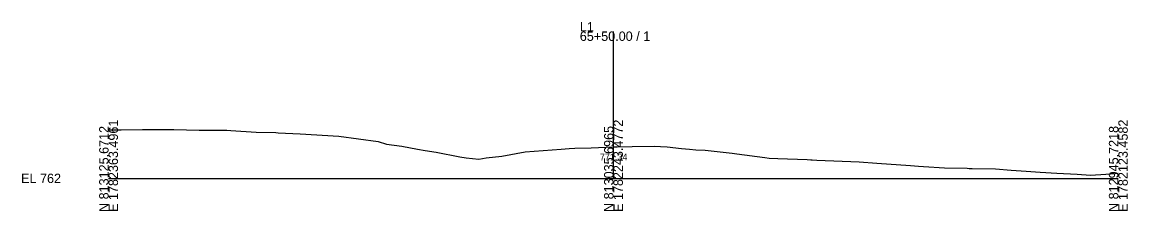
# Model space of a CAD drawing. Extents: x 5574 to 10203, y -10 to 9546.
# Drawn here: x 7574.3 to 7902.8, y 2990.3 to 3046.5 of the extents above; entities that cross this region are included whole.
import ezdxf

# ---------------------------------------------------------------- set-up
doc = ezdxf.new("R2010")
doc.units = 0
for name, color, linetype in [('Exist Cross Section Cell', 7, 'Continuous'), ('Exist XS Center Line Elevation Label', 7, 'Continuous'), ('Exist XS Ground Line', 7, 'Continuous')]:
    doc.layers.add(name, color=color, linetype=linetype)

msp = doc.modelspace()

# ---------------------------------------------------------------- linework, layer by layer
at = {"layer": 'Exist Cross Section Cell'}
for p, q in [((7750, 3000), (7750, 3043.71)), ((7600, 3000), (7750, 3000)), ((7750, 3000), (7900, 3000))]:
    msp.add_line(p, q, dxfattribs=at)
at = {"layer": 'Exist XS Ground Line'}
for p, q in [((7600, 3014.43), (7603.78, 3014.44)), ((7603.78, 3014.44), (7610.06, 3014.52)), ((7610.06, 3014.52), (7617.29, 3014.57)), ((7617.29, 3014.57), (7619.39, 3014.55)), ((7619.39, 3014.55), (7626.94, 3014.3)), ((7626.94, 3014.3), (7633.7, 3014.32)), ((7633.7, 3014.32), (7635.09, 3014.3)), ((7635.09, 3014.3), (7636.33, 3014.26)), ((7636.33, 3014.26), (7643.86, 3013.72)), ((7643.86, 3013.72), (7649.69, 3013.6)), ((7649.69, 3013.6), (7650.4, 3013.58)), ((7650.4, 3013.58), (7656.88, 3013.29)), ((7656.88, 3013.29), (7668.44, 3012.55)), ((7668.44, 3012.55), (7680.14, 3010.95)), ((7680.14, 3010.95), (7682.61, 3010.19)), ((7682.61, 3010.19), (7687.13, 3009.61)), ((7687.13, 3009.61), (7691.73, 3008.65)), ((7750, 3009.34), (7751.08, 3009.38)), ((7751.08, 3009.38), (7755.59, 3009.48)), ((7755.59, 3009.48), (7762.08, 3009.61)), ((7762.08, 3009.61), (7763.98, 3009.52)), ((7763.98, 3009.52), (7765.99, 3009.43)), ((7765.99, 3009.43), (7770.26, 3008.88)), ((7691.73, 3008.65), (7694.07, 3008.33)), ((7694.07, 3008.33), (7697.37, 3007.76)), ((7697.37, 3007.76), (7704.31, 3006.41)), ((7704.31, 3006.41), (7706.24, 3006.13)), ((7706.24, 3006.13), (7709.96, 3005.76)), ((7712.14, 3006.06), (7716.88, 3006.62)), ((7716.88, 3006.62), (7723.79, 3007.87)), ((7723.79, 3007.87), (7734.44, 3008.69)), ((7734.44, 3008.69), (7736.83, 3008.85)), ((7736.83, 3008.85), (7738.53, 3008.95)), ((7738.53, 3008.95), (7743.33, 3009.11)), ((7743.33, 3009.11), (7750, 3009.34)), ((7770.26, 3008.88), (7772.64, 3008.65)), ((7772.64, 3008.65), (7774.48, 3008.53)), ((7774.48, 3008.53), (7777.24, 3008.43)), ((7777.24, 3008.43), (7785.28, 3007.45)), ((7785.28, 3007.45), (7786.65, 3007.27)), ((7786.65, 3007.27), (7794.93, 3006.16)), ((7794.93, 3006.16), (7796.27, 3006.01)), ((7709.96, 3005.76), (7712.14, 3006.06)), ((7796.27, 3006.01), (7798.83, 3005.92)), ((7798.83, 3005.92), (7807.53, 3005.57)), ((7807.53, 3005.57), (7808.66, 3005.53)), ((7808.66, 3005.53), (7809.04, 3005.52)), ((7809.04, 3005.52), (7810.4, 3005.45)), ((7810.4, 3005.45), (7823.04, 3004.89)), ((7823.04, 3004.89), (7828.24, 3004.53)), ((7828.24, 3004.53), (7838.24, 3003.78)), ((7838.24, 3003.78), (7840.62, 3003.64)), ((7840.62, 3003.64), (7842.08, 3003.52)), ((7842.08, 3003.52), (7848.34, 3003.16)), ((7848.34, 3003.16), (7855.05, 3002.99)), ((7855.05, 3002.99), (7855.72, 3002.97)), ((7855.72, 3002.97), (7856.54, 3002.95)), ((7856.54, 3002.95), (7863.5, 3002.81)), ((7863.5, 3002.81), (7868.13, 3002.4)), ((7868.13, 3002.4), (7872.66, 3002.12)), ((7872.66, 3002.12), (7876.76, 3001.86)), ((7876.76, 3001.86), (7881.75, 3001.58)), ((7881.75, 3001.58), (7887.75, 3001.25)), ((7887.75, 3001.25), (7891.7, 3000.99)), ((7891.7, 3000.99), (7896.25, 3001.23)), ((7896.25, 3001.23), (7899.1, 3001.44)), ((7899.1, 3001.44), (7900, 3001.59))]:
    msp.add_line(p, q, dxfattribs=at)

# ---------------------------------------------------------------- texts
at = {"layer": 'Exist Cross Section Cell'}
for s, p in [('L1', (7740, 3043.71)), ('65+50.00 / 1', (7740, 3040.91)), ('EL 762', (7574, 2998.6))]:
    msp.add_text(s, height=2.8, dxfattribs=at).set_placement(p)
for s, p in [('E 1782363.4961', (7602.8, 2990)), ('E 1782243.4772', (7752.8, 2990)), ('E 1782123.4582', (7902.8, 2990)), ('N 813125.6712', (7600, 2990)), ('N 813035.6965', (7750, 2990)), ('N 812945.7218', (7900, 2990))]:
    msp.add_text(s, height=2.8, rotation=90, dxfattribs=at).set_placement(p)
at = {"layer": 'Exist XS Center Line Elevation Label'}
msp.add_text('771.34', height=2, dxfattribs=at).set_placement((7745.96, 3005.34))

doc.saveas('drawing.dxf')
